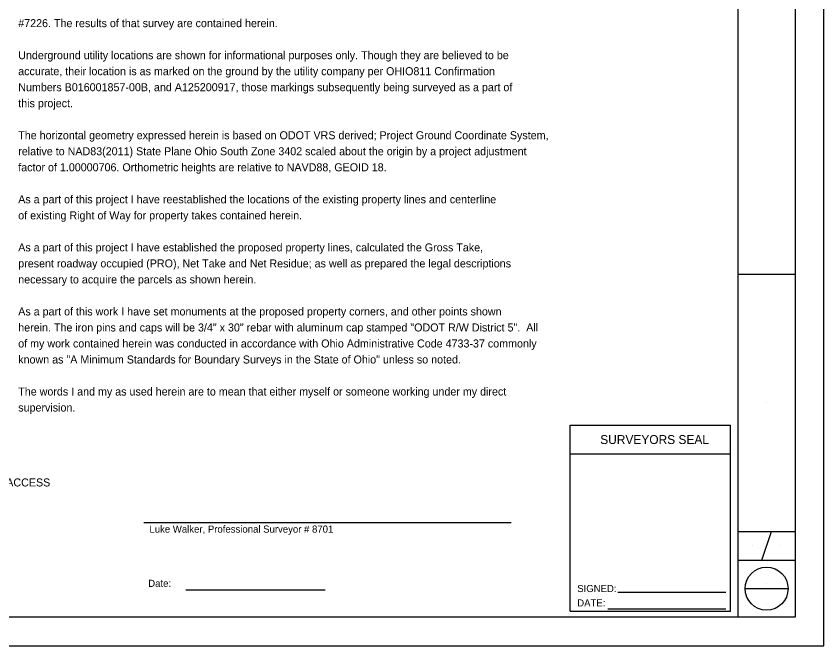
# Model space of a CAD drawing. Extents: x 0 to 34, y 0 to 22.
# Drawn here: x 19.88 to 34, y 0 to 11.01 of the extents above; entities that cross this region are included whole.
import ezdxf

# ---------------------------------------------------------------- set-up
doc = ezdxf.new("R2010")
doc.units = 0
for name, color, linetype in [('SH_Border', 7, 'Continuous'), ('SH_Cut_Line', 7, 'Continuous'), ('SH_Data', 7, 'Continuous'), ('SH_Text', 7, 'Continuous')]:
    doc.layers.add(name, color=color, linetype=linetype)

msp = doc.modelspace()

# ---------------------------------------------------------------- linework, layer by layer
at = {"layer": 'SH_Border'}
for p, q in [((32.5, 0.5), (32.5, 21.5)), ((32.5, 6.5), (33.5, 6.5)), ((32.5, 2), (33.5, 2)), ((32.917, 1.5), (33.083, 2)), ((32.5, 1.5), (33.5, 1.5))]:
    msp.add_line(p, q, dxfattribs=at)
msp.add_lwpolyline([(2, 21.5), (33.5, 21.5), (33.5, 0.5), (2, 0.5)], close=True, dxfattribs=at)
at = {"layer": 'SH_Cut_Line'}
msp.add_lwpolyline([(0, 0), (34, 0), (34, 22), (0, 22)], close=True, dxfattribs=at)
at = {"layer": 'SH_Data'}
for p, q in [((33, 4.25), (33, 4.25)), ((29.564, 0.607), (29.564, 3.857)), ((29.564, 3.857), (32.365, 3.857)), ((32.365, 0.607), (32.365, 3.857)), ((29.564, 3.357), (32.365, 3.357)), ((32.75, 1.75), (32.75, 1.75)), ((33.25, 1.75), (33.25, 1.75)), ((32.625, 1), (33.375, 1)), ((33, 1.085), (33, 1.085)), ((30.398, 0.939), (32.286, 0.939)), ((33, 0.745), (33, 0.745)), ((29.564, 0.607), (32.365, 0.607)), ((30.222, 0.65), (32.286, 0.65))]:
    msp.add_line(p, q, dxfattribs=at)
msp.add_circle((33, 1), 0.375, dxfattribs=at)
at = {"layer": 'SH_Text'}
for p, q in [((22.113, 2.157), (28.534, 2.157)), ((22.842, 0.979), (25.28, 0.979))]:
    msp.add_line(p, q, dxfattribs=at)

# ---------------------------------------------------------------- texts
at = {"layer": 'SH_Data'}
for s, height, p in [('SURVEYORS SEAL', 0.15602, (30.09, 3.529)), ('SIGNED:', 0.125, (29.688, 0.94)), ('DATE:  ', 0.125, (29.688, 0.688))]:
    msp.add_text(s, height=height, dxfattribs=at).set_placement(p)
at = {"layer": 'SH_Text'}
for s, height, p in [('#7226. The results of that survey are contained herein. ', 0.14001, (19.914, 10.818)), ('Underground utility locations are shown for informational purposes only. Though they are believed to be ', 0.140014, (19.914, 10.258)), ('accurate, their location is as marked on the ground by the utility company per OHIO811 Confirmation ', 0.14001, (19.914, 9.978)), ('Numbers B016001857-00B, and A125200917, those markings subsequently being surveyed as a part of', 0.14001, (19.914, 9.698)), ('this project. ', 0.14001, (19.914, 9.418)), ('The horizontal geometry expressed herein is based on ODOT VRS derived; Project Ground Coordinate System, ', 0.140014, (19.914, 8.858)), ('relative to NAD83(2011) State Plane Ohio South Zone 3402 scaled about the origin by a project adjustment ', 0.140014, (19.914, 8.578)), ('factor of 1.00000706. Orthometric heights are relative to NAVD88, GEOID 18.', 0.14001, (19.914, 8.298)), ('As a part of this project I have reestablished the locations of the existing property lines and centerline ', 0.140014, (19.914, 7.738)), ('of existing Right of Way for property takes contained herein. ', 0.14001, (19.914, 7.457)), ('As a part of this project I have established the proposed property lines, calculated the Gross Take, ', 0.140014, (19.914, 6.897)), ('present roadway occupied (PRO), Net Take and Net Residue; as well as prepared the legal descriptions ', 0.140014, (19.914, 6.617)), ('necessary to acquire the parcels as shown herein. ', 0.14001, (19.914, 6.337)), ('As a part of this work I have set monuments at the proposed property corners, and other points shown ', 0.140014, (19.914, 5.777)), ('herein. The iron pins and caps will be 3/4" x 30" rebar with aluminum cap stamped "ODOT R/W District 5".  All ', 0.140014, (19.914, 5.497)), ('of my work contained herein was conducted in accordance with Ohio Administrative Code 4733-37 commonly ', 0.140014, (19.914, 5.217)), ('known as "A Minimum Standards for Boundary Surveys in the State of Ohio" unless so noted. ', 0.14001, (19.914, 4.937)), ('The words I and my as used herein are to mean that either myself or someone working under my direct ', 0.14001, (19.914, 4.377)), ('supervision. ', 0.14001, (19.914, 4.097)), ('WL = FEE SIMPLE WITH LIMITATION OF ACCESS', 0.14, (16.111, 2.787)), ('Luke Walker, Professional Surveyor # 8701', 0.12501, (22.208, 1.979)), ('Date:  ', 0.125, (22.187, 1.031))]:
    msp.add_text(s, height=height, dxfattribs=at).set_placement(p)

doc.saveas('drawing.dxf')
